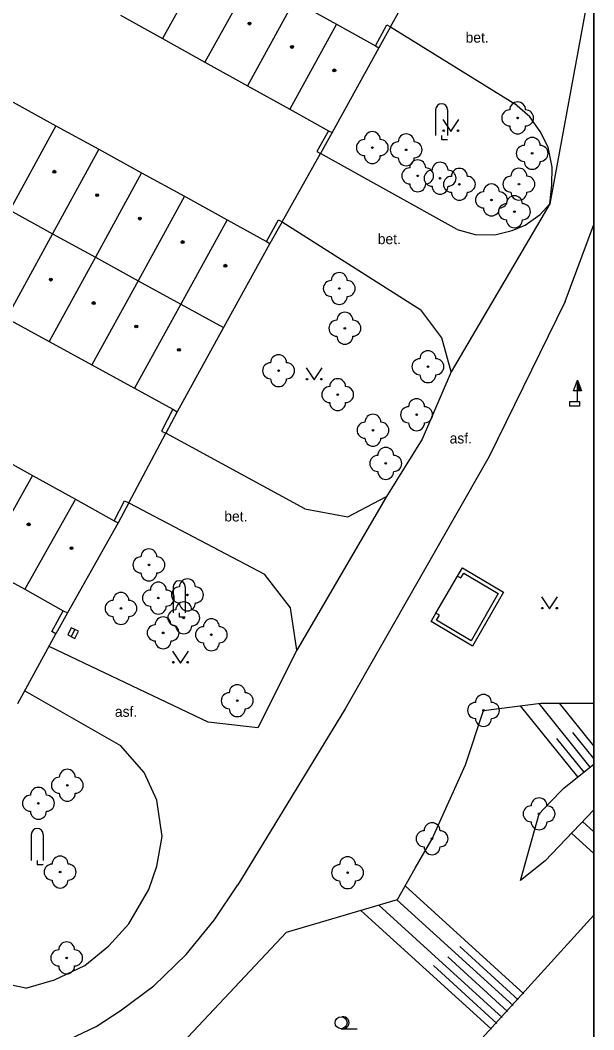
# Model space of a CAD drawing. Extents: x -598233 to -596890, y -1157848 to -1156431.
# Drawn here: x -596926.4 to -596890.5, y -1157763.6 to -1157700.3 of the extents above; entities that cross this region are included whole.
import ezdxf

# ---------------------------------------------------------------- set-up
doc = ezdxf.new("R2010")
doc.units = 0
for name, color, linetype in [('Level 10', 7, 'Continuous'), ('Level 11', 7, 'Continuous'), ('Level 14', 7, 'Continuous'), ('Level 15', 7, 'Continuous'), ('Level 22', 7, 'Continuous'), ('Level 24', 7, 'Continuous'), ('Level 25', 7, 'Continuous'), ('Level 27', 7, 'Continuous'), ('Level 36', 7, 'Continuous'), ('Level 39', 7, 'Continuous'), ('Level 40', 7, 'Continuous'), ('Level 5', 7, 'Continuous'), ('Level 7', 7, 'Continuous'), ('Level 8', 7, 'Continuous'), ('Vrstva 60', 7, 'Continuous'), ('zajmove_uzemi', 7, 'Continuous')]:
    doc.layers.add(name, color=color, linetype=linetype)

msp = doc.modelspace()

# ---------------------------------------------------------------- linework, layer by layer
at = {"layer": 'Level 10'}
msp.add_line((-596892.26, -1157717.92), (-596890.4624, -1157713.1005), dxfattribs=at)
for points in [[(-596903.2, -1157700.71), (-596895.4, -1157705.54)], [(-596893.21, -1157711.8), (-596893.1, -1157710.63), (-596893.07, -1157709.5), (-596893.32, -1157708.26), (-596893.82, -1157707.26), (-596894.4699, -1157706.35), (-596895.4, -1157705.54)], [(-596899.01, -1157713.4099), (-596907.58, -1157708.64)], [(-596899.01, -1157713.4099), (-596897.9, -1157713.7199), (-596896.6599, -1157713.74), (-596895.57, -1157713.48), (-596894.75, -1157713.13), (-596893.82, -1157712.4699), (-596893.21, -1157711.8)], [(-596909.98, -1157712.93), (-596901.29, -1157718.44)], [(-596892.26, -1157717.92), (-596897.01, -1157727.64), (-596906.03, -1157743.46), (-596912.75, -1157754.48)], [(-596899.39, -1157722.34), (-596899.9699, -1157720.21), (-596901.29, -1157718.44)], [(-596899.39, -1157722.34), (-596901.2199, -1157726.56), (-596903.45, -1157730.14)], [(-596908.55, -1157730.9099), (-596917.27, -1157726.17)], [(-596908.55, -1157730.9099), (-596905.87, -1157731.42), (-596903.45, -1157730.14)], [(-596919.58, -1157730.55), (-596911.09, -1157735.01)], [(-596909.06, -1157739.77), (-596909.45, -1157737.12), (-596911.09, -1157735.01)], [(-596909.06, -1157739.77), (-596911.49, -1157744.65), (-596914.61, -1157744.29), (-596924.57, -1157739.54)], [(-596926.09, -1157742.33), (-596920.11, -1157745.75)], [(-596926.02, -1157760.95), (-596924.23, -1157760.44), (-596922.34, -1157759.53), (-596920.82, -1157758.31), (-596919.57, -1157756.93), (-596918.33, -1157754.78), (-596917.83, -1157753.31), (-596917.5, -1157751.45), (-596917.82, -1157749.18), (-596918.62, -1157747.44), (-596920.11, -1157745.75)], [(-596926.87, -1157764.92), (-596923.3, -1157764.1599), (-596921.63, -1157763.36), (-596920.12, -1157762.37), (-596918.01, -1157760.8), (-596915.99, -1157758.84), (-596914.23, -1157756.7), (-596912.75, -1157754.48)], [(-596926.02, -1157760.95), (-596935.48, -1157759)]]:
    msp.add_lwpolyline(points, dxfattribs=at)
at = {"layer": 'Level 11'}
msp.add_line((-596890.4624, -1157696.83), (-596893.21, -1157711.8), dxfattribs=at)
for points in [[(-596893.21, -1157711.8), (-596899.39, -1157722.34)], [(-596903.45, -1157730.14), (-596909.06, -1157739.77)], [(-596900.35, -1157737.46), (-596898.99, -1157735.13)]]:
    msp.add_lwpolyline(points, dxfattribs=at)
at = {"layer": 'Level 14'}
for points in [[(-596900.59, -1157751.59), (-596898.5, -1157746.96), (-596897.37, -1157743.55), (-596893.77, -1157743.1), (-596890.4624, -1157743.0861)], [(-596893.27, -1157749.39), (-596892.32, -1157748.41), (-596890.4624, -1157746.9178)], [(-596895.06, -1157754.21), (-596893.89, -1157750.03), (-596893.27, -1157749.39)], [(-596890.4624, -1157749.7778), (-596893.51, -1157752.97), (-596895.06, -1157754.21)], [(-596901.64, -1157753.43), (-596900.59, -1157751.59)], [(-596931.46, -1157795.75), (-596930.64, -1157790), (-596929.99, -1157784.52), (-596931.05, -1157778.72), (-596927.22, -1157770.82), (-596926.09, -1157769.73), (-596923.59, -1157770.16), (-596920.73, -1157768.54), (-596916.2, -1157764.35), (-596909.71, -1157757.45), (-596902.75, -1157755.4), (-596901.64, -1157753.43)]]:
    msp.add_lwpolyline(points, dxfattribs=at)
at = {"layer": 'Level 15'}
for p, q in [((-596890.4624, -1157745.7706), (-596892.61, -1157743.1)), ((-596890.4624, -1157746.5656), (-596891.77, -1157744.94)), ((-596890.4624, -1157749.8159), (-596890.48, -1157749.8)), ((-596890.4624, -1157751.1628), (-596891.17, -1157750.52)), ((-596890.4624, -1157752.5105), (-596891.86, -1157751.24))]:
    msp.add_line(p, q, dxfattribs=at)
for points in [[(-596891.46, -1157747.72), (-596895.05, -1157743.26)], [(-596890.68, -1157747.1), (-596893.88, -1157743.11)], [(-596891.07, -1157747.41), (-596892.77, -1157745.3)], [(-596894.85, -1157761.32), (-596902.27, -1157754.55)], [(-596895.52, -1157762.05), (-596902.8, -1157755.42)], [(-596896.87, -1157763.53), (-596905.05, -1157756.08)], [(-596896.2, -1157762.79), (-596903.92, -1157755.75)], [(-596895.19, -1157761.68), (-596898.85, -1157758.34)], [(-596895.86, -1157762.42), (-596899.61, -1157759)], [(-596896.54, -1157763.16), (-596900.51, -1157759.54)]]:
    msp.add_lwpolyline(points, dxfattribs=at)
at = {"layer": 'Level 22'}
for centre in [(-596895.23, -1157706.42), (-596904.33, -1157708.28), (-596902.21, -1157708.42), (-596894.32, -1157708.64), (-596901.49, -1157710.05), (-596900.09, -1157710.2), (-596898.88, -1157710.58), (-596895.15, -1157710.57), (-596896.87, -1157711.56), (-596895.43, -1157712.3), (-596906.4, -1157717.11), (-596906.05, -1157719.6), (-596900.85, -1157722.01), (-596910.2, -1157722.26), (-596906.5, -1157723.76), (-596901.56, -1157725.02), (-596904.29, -1157725.99), (-596903.49, -1157728.07), (-596918.32, -1157734.43), (-596917.73, -1157736.51), (-596915.91, -1157736.31), (-596920.07, -1157737.16), (-596916.14, -1157737.75), (-596917.43, -1157738.69), (-596914.41, -1157738.81), (-596912.79, -1157742.94), (-596897.37, -1157743.55), (-596923.43, -1157748.24), (-596925.24, -1157749.37), (-596893.89, -1157750.03), (-596900.59, -1157751.59), (-596923.88, -1157753.68), (-596905.88, -1157753.72), (-596923.47, -1157759.06)]:
    msp.add_circle(centre, 0.05, dxfattribs=at)
for centre, start, end in [((-596895.23, -1157705.92), 0, 180), ((-596895.73, -1157706.42), 90, 270), ((-596894.73, -1157706.42), 270, 90), ((-596904.33, -1157707.78), 0, 180), ((-596902.21, -1157707.92), 0, 180), ((-596895.23, -1157706.92), 180, 0), ((-596904.83, -1157708.28), 90, 270), ((-596903.83, -1157708.28), 270, 90), ((-596902.71, -1157708.42), 90, 270), ((-596901.71, -1157708.42), 270, 90), ((-596894.32, -1157708.14), 0, 180), ((-596894.82, -1157708.64), 90, 270), ((-596893.82, -1157708.64), 270, 90), ((-596904.33, -1157708.78), 180, 0), ((-596902.21, -1157708.92), 180, 0), ((-596901.49, -1157709.55), 0, 180), ((-596900.09, -1157709.7), 0, 180), ((-596894.32, -1157709.14), 180, 0), ((-596901.99, -1157710.05), 90, 270), ((-596900.59, -1157710.2), 90, 270), ((-596900.99, -1157710.05), 270, 90), ((-596899.59, -1157710.2), 270, 90), ((-596898.88, -1157710.08), 0, 180), ((-596895.15, -1157710.07), 0, 180), ((-596901.49, -1157710.55), 180, 0), ((-596899.38, -1157710.58), 90, 270), ((-596898.38, -1157710.58), 270, 90), ((-596896.87, -1157711.06), 0, 180), ((-596895.65, -1157710.57), 90, 270), ((-596894.65, -1157710.57), 270, 90), ((-596900.09, -1157710.7), 180, 0), ((-596898.88, -1157711.08), 180, 0), ((-596897.37, -1157711.56), 90, 270), ((-596896.37, -1157711.56), 270, 90), ((-596895.15, -1157711.07), 180, 0), ((-596895.93, -1157712.3), 90, 270), ((-596895.43, -1157711.8), 0, 180), ((-596894.93, -1157712.3), 270, 90), ((-596896.87, -1157712.06), 180, 0), ((-596895.43, -1157712.8), 180, 0), ((-596906.4, -1157716.61), 0, 180), ((-596906.9, -1157717.11), 90, 270), ((-596905.9, -1157717.11), 270, 90), ((-596906.4, -1157717.61), 180, 0), ((-596906.05, -1157719.1), 0, 180), ((-596906.55, -1157719.6), 90, 270), ((-596905.55, -1157719.6), 270, 90), ((-596906.05, -1157720.1), 180, 0), ((-596910.2, -1157721.76), 0, 180), ((-596900.85, -1157721.51), 0, 180), ((-596910.7, -1157722.26), 90, 270), ((-596909.7, -1157722.26), 270, 90), ((-596901.35, -1157722.01), 90, 270), ((-596900.35, -1157722.01), 270, 90), ((-596900.85, -1157722.51), 180, 0), ((-596910.2, -1157722.76), 180, 0), ((-596907, -1157723.76), 90, 270), ((-596906.5, -1157723.26), 0, 180), ((-596906, -1157723.76), 270, 90), ((-596906.5, -1157724.26), 180, 0), ((-596902.06, -1157725.02), 90, 270), ((-596901.56, -1157724.52), 0, 180), ((-596901.06, -1157725.02), 270, 90), ((-596904.29, -1157725.49), 0, 180), ((-596904.79, -1157725.99), 90, 270), ((-596903.79, -1157725.99), 270, 90), ((-596901.56, -1157725.52), 180, 0), ((-596904.29, -1157726.49), 180, 0), ((-596903.49, -1157727.57), 0, 180), ((-596903.99, -1157728.07), 90, 270), ((-596902.99, -1157728.07), 270, 90), ((-596903.49, -1157728.57), 180, 0), ((-596918.32, -1157733.93), 0, 180), ((-596918.82, -1157734.43), 90, 270), ((-596917.82, -1157734.43), 270, 90), ((-596918.32, -1157734.93), 180, 0), ((-596915.91, -1157735.81), 0, 180), ((-596917.73, -1157736.01), 0, 180), ((-596916.41, -1157736.31), 90, 270), ((-596915.41, -1157736.31), 270, 90), ((-596920.07, -1157736.66), 0, 180), ((-596918.23, -1157736.51), 90, 270), ((-596917.23, -1157736.51), 270, 90), ((-596920.57, -1157737.16), 90, 270), ((-596919.57, -1157737.16), 270, 90), ((-596917.73, -1157737.01), 180, 0), ((-596916.14, -1157737.25), 0, 180), ((-596915.91, -1157736.81), 180, 0), ((-596920.07, -1157737.66), 180, 0), ((-596917.43, -1157738.19), 0, 180), ((-596916.64, -1157737.75), 90, 270), ((-596915.64, -1157737.75), 270, 90), ((-596914.41, -1157738.31), 0, 180), ((-596917.93, -1157738.69), 90, 270), ((-596916.93, -1157738.69), 270, 90), ((-596916.14, -1157738.25), 180, 0), ((-596914.91, -1157738.81), 90, 270), ((-596913.91, -1157738.81), 270, 90), ((-596917.43, -1157739.19), 180, 0), ((-596914.41, -1157739.31), 180, 0), ((-596912.79, -1157742.44), 0, 180), ((-596913.29, -1157742.94), 90, 270), ((-596912.29, -1157742.94), 270, 90), ((-596897.37, -1157743.05), 0, 180), ((-596912.79, -1157743.44), 180, 0), ((-596897.87, -1157743.55), 90, 270), ((-596896.87, -1157743.55), 270, 90), ((-596897.37, -1157744.05), 180, 0), ((-596923.43, -1157747.74), 0, 180), ((-596923.93, -1157748.24), 90, 270), ((-596922.93, -1157748.24), 270, 90), ((-596925.24, -1157748.87), 0, 180), ((-596925.74, -1157749.37), 90, 270), ((-596924.74, -1157749.37), 270, 90), ((-596923.43, -1157748.74), 180, 0), ((-596893.89, -1157749.53), 0, 180), ((-596925.24, -1157749.87), 180, 0), ((-596894.39, -1157750.03), 90, 270), ((-596893.39, -1157750.03), 270, 90), ((-596901.09, -1157751.59), 90, 270), ((-596900.59, -1157751.09), 0, 180), ((-596900.09, -1157751.59), 270, 90), ((-596893.89, -1157750.53), 180, 0), ((-596900.59, -1157752.09), 180, 0), ((-596923.88, -1157753.18), 0, 180), ((-596905.88, -1157753.22), 0, 180), ((-596924.38, -1157753.68), 90, 270), ((-596923.38, -1157753.68), 270, 90), ((-596906.38, -1157753.72), 90, 270), ((-596905.38, -1157753.72), 270, 90), ((-596923.88, -1157754.18), 180, 0), ((-596905.88, -1157754.22), 180, 0), ((-596923.47, -1157758.56), 0, 180), ((-596923.97, -1157759.06), 90, 270), ((-596922.97, -1157759.06), 270, 90), ((-596923.47, -1157759.56), 180, 0)]:
    msp.add_arc(centre, 0.5, start, end, dxfattribs=at)
at = {"layer": 'Level 24'}
msp.add_lwpolyline([(-596891.36, -1157724.19), (-596891.36, -1157724.49), (-596891.96, -1157724.49), (-596891.96, -1157724.19), (-596891.36, -1157724.19)], dxfattribs=at)
at = {"layer": 'Level 25'}
for p, q in [((-596891.742, -1157723.528), (-596891.49, -1157722.854)), ((-596891.49, -1157723.528), (-596891.742, -1157723.528)), ((-596891.49, -1157724.18), (-596891.49, -1157723.53))]:
    msp.add_line(p, q, dxfattribs=at)
for points in [[(-596891.24, -1157723.53), (-596891.49, -1157723.53), (-596891.49, -1157722.854), (-596891.49, -1157722.854)], [(-596891.297, -1157723.49), (-596891.45, -1157723.49), (-596891.45, -1157723.077)], [(-596891.355, -1157723.45), (-596891.41, -1157723.45), (-596891.41, -1157723.301)]]:
    msp.add_lwpolyline(points, close=True, dxfattribs=at)
at = {"layer": 'Level 27'}
msp.add_line((-596923.1775, -1157738.9257), (-596922.9625, -1157738.4743), dxfattribs=at)
msp.add_lwpolyline([(-596922.9517, -1157739.0332), (-596922.7368, -1157738.5817), (-596923.1883, -1157738.3668), (-596923.4032, -1157738.8183)], close=True, dxfattribs=at)
at = {"layer": 'Level 36'}
for p, q in [((-596900.365, -1157705.905), (-596900.365, -1157707.53)), ((-596899.615, -1157705.905), (-596899.615, -1157707.53)), ((-596916.795, -1157735.805), (-596916.795, -1157737.43)), ((-596916.045, -1157735.805), (-596916.045, -1157737.43)), ((-596925.685, -1157751.325), (-596925.685, -1157752.95)), ((-596924.935, -1157751.325), (-596924.935, -1157752.95)), ((-596906.29, -1157763.495), (-596905.29, -1157763.495))]:
    msp.add_line(p, q, dxfattribs=at)
for points in [[(-596899.91, -1157706.52), (-596899.41, -1157707.27), (-596898.91, -1157706.52)], [(-596899.99, -1157707.53), (-596899.99, -1157707.78), (-596899.615, -1157707.78)], [(-596908.4699, -1157722.09), (-596907.9699, -1157722.84), (-596907.4699, -1157722.09)], [(-596893.73, -1157736.44), (-596893.23, -1157737.19), (-596892.73, -1157736.44)], [(-596916.42, -1157737.43), (-596916.42, -1157737.68), (-596916.045, -1157737.68)], [(-596916.84, -1157739.83), (-596916.34, -1157740.58), (-596915.84, -1157739.83)], [(-596925.31, -1157752.95), (-596925.31, -1157753.2), (-596924.935, -1157753.2)]]:
    msp.add_lwpolyline(points, dxfattribs=at)
for centre, radius in [((-596899.8602, -1157707.2198), 0.05), ((-596898.9608, -1157707.2198), 0.05), ((-596908.4201, -1157722.7898), 0.05), ((-596907.5207, -1157722.7898), 0.05), ((-596893.6802, -1157737.1398), 0.05), ((-596892.7808, -1157737.1398), 0.05), ((-596916.7902, -1157740.5298), 0.05), ((-596915.8908, -1157740.5298), 0.05), ((-596906.29, -1157763.1196), 0.375)]:
    msp.add_circle(centre, radius, dxfattribs=at)
for centre, start, end in [((-596899.9903, -1157705.9046), 0, 180), ((-596916.4203, -1157735.8046), 0, 180), ((-596925.3103, -1157751.3246), 0, 180), ((-596906.165, -1157763.1196), 260.405931, 99.594069)]:
    msp.add_arc(centre, 0.375, start, end, dxfattribs=at)
at = {"layer": 'Level 39'}
for centre, radius in [((-596912.02, -1157700.51), 0.09), ((-596912.02, -1157700.51), 0.0398), ((-596909.36, -1157701.9699), 0.09), ((-596909.36, -1157701.9699), 0.0398), ((-596906.71, -1157703.44), 0.09), ((-596906.71, -1157703.44), 0.0398), ((-596924.24, -1157709.79), 0.09), ((-596924.24, -1157709.79), 0.0398), ((-596921.56, -1157711.26), 0.09), ((-596921.56, -1157711.26), 0.0398), ((-596918.89, -1157712.73), 0.09), ((-596918.89, -1157712.73), 0.0398), ((-596916.21, -1157714.2), 0.09), ((-596916.21, -1157714.2), 0.0398), ((-596913.53, -1157715.68), 0.09), ((-596913.53, -1157715.68), 0.0398), ((-596924.46, -1157716.55), 0.09), ((-596924.46, -1157716.55), 0.0398), ((-596921.78, -1157718.02), 0.09), ((-596921.78, -1157718.02), 0.0398), ((-596919.11, -1157719.49), 0.09), ((-596919.11, -1157719.49), 0.0398), ((-596916.44, -1157720.95), 0.09), ((-596916.44, -1157720.95), 0.0398), ((-596925.85, -1157731.89), 0.09), ((-596925.85, -1157731.89), 0.0398), ((-596923.17, -1157733.38), 0.09), ((-596923.17, -1157733.38), 0.0398)]:
    msp.add_circle(centre, radius, dxfattribs=at)
at = {"layer": 'Level 5'}
for points in [[(-596914.53, -1157696.14), (-596917.46, -1157701.45)], [(-596911.88, -1157697.61), (-596914.81, -1157702.92)], [(-596909.2199, -1157699.08), (-596912.15, -1157704.4)], [(-596909.2199, -1157699.08), (-596906.57, -1157700.55)], [(-596920.11, -1157699.98), (-596917.46, -1157701.45)], [(-596906.57, -1157700.55), (-596909.5, -1157705.87)], [(-596906.57, -1157700.55), (-596904.14, -1157701.9)], [(-596917.46, -1157701.45), (-596914.81, -1157702.92)], [(-596903.92, -1157702.02), (-596906.85, -1157707.34)], [(-596904.14, -1157701.9), (-596903.92, -1157702.02)], [(-596914.81, -1157702.92), (-596912.15, -1157704.4)], [(-596912.15, -1157704.4), (-596909.5, -1157705.87)], [(-596926.82, -1157705.44), (-596924.14, -1157706.9099)], [(-596909.5, -1157705.87), (-596907.07, -1157707.2199)], [(-596924.14, -1157706.9099), (-596927.02, -1157712.2)], [(-596924.14, -1157706.9099), (-596921.46, -1157708.38)], [(-596907.07, -1157707.2199), (-596906.85, -1157707.34)], [(-596921.46, -1157708.38), (-596924.35, -1157713.68)], [(-596921.46, -1157708.38), (-596918.78, -1157709.86)], [(-596918.78, -1157709.86), (-596921.67, -1157715.15)], [(-596918.78, -1157709.86), (-596916.1, -1157711.33)], [(-596916.1, -1157711.33), (-596919, -1157716.62)], [(-596916.1, -1157711.33), (-596913.42, -1157712.81)], [(-596927.02, -1157712.2), (-596924.35, -1157713.68)], [(-596913.42, -1157712.81), (-596916.33, -1157718.09)], [(-596913.42, -1157712.81), (-596910.96, -1157714.1599)], [(-596924.35, -1157713.68), (-596927.24, -1157718.96)], [(-596924.35, -1157713.68), (-596921.67, -1157715.15)], [(-596910.74, -1157714.28), (-596913.65, -1157719.56)], [(-596910.96, -1157714.1599), (-596910.74, -1157714.28)], [(-596921.67, -1157715.15), (-596924.57, -1157720.43)], [(-596921.67, -1157715.15), (-596919, -1157716.62)], [(-596919, -1157716.62), (-596921.9, -1157721.9)], [(-596919, -1157716.62), (-596916.33, -1157718.09)], [(-596916.33, -1157718.09), (-596919.23, -1157723.36)], [(-596916.33, -1157718.09), (-596913.65, -1157719.56)], [(-596927.24, -1157718.96), (-596924.57, -1157720.43)], [(-596913.65, -1157719.56), (-596916.56, -1157724.83)], [(-596924.57, -1157720.43), (-596921.9, -1157721.9)], [(-596921.9, -1157721.9), (-596919.23, -1157723.36)], [(-596919.23, -1157723.36), (-596916.82, -1157724.68)], [(-596916.82, -1157724.68), (-596916.56, -1157724.83)], [(-596928.28, -1157727.35), (-596925.6, -1157728.83)], [(-596925.6, -1157728.83), (-596928.78, -1157734.49)], [(-596925.6, -1157728.83), (-596922.92, -1157730.32)], [(-596922.92, -1157730.32), (-596926.1, -1157735.96)], [(-596922.92, -1157730.32), (-596920.5, -1157731.6599)], [(-596920.24, -1157731.8), (-596923.42, -1157737.44)], [(-596920.5, -1157731.6599), (-596920.24, -1157731.8)], [(-596928.78, -1157734.49), (-596926.1, -1157735.96)], [(-596926.1, -1157735.96), (-596923.68, -1157737.3)], [(-596923.68, -1157737.3), (-596923.42, -1157737.44)]]:
    msp.add_lwpolyline(points, dxfattribs=at)
at = {"layer": 'Level 7'}
for points in [[(-596904.14, -1157701.9), (-596903.42, -1157700.58), (-596903.2, -1157700.71)], [(-596903.2, -1157700.71), (-596903.92, -1157702.02)], [(-596907.07, -1157707.2199), (-596907.8, -1157708.52), (-596907.58, -1157708.64)], [(-596906.85, -1157707.34), (-596907.58, -1157708.64)], [(-596910.96, -1157714.1599), (-596910.2, -1157712.81), (-596909.98, -1157712.93)], [(-596909.98, -1157712.93), (-596910.74, -1157714.28)], [(-596916.82, -1157724.68), (-596917.54, -1157726.04), (-596917.27, -1157726.17)], [(-596916.56, -1157724.83), (-596917.27, -1157726.17)], [(-596920.5, -1157731.6599), (-596919.84, -1157730.4099), (-596919.58, -1157730.55)], [(-596919.58, -1157730.55), (-596920.24, -1157731.8)], [(-596898.69, -1157734.61), (-596896.11, -1157736.14), (-596898.06, -1157739.52), (-596900.65, -1157737.98), (-596900.35, -1157737.46)], [(-596898.99, -1157735.13), (-596898.69, -1157734.61)], [(-596898.99, -1157735.13), (-596898.78, -1157735.25), (-596898.6, -1157734.95), (-596896.45, -1157736.23), (-596898.15, -1157739.18), (-596900.31, -1157737.89), (-596900.13, -1157737.59), (-596900.35, -1157737.46)], [(-596924.14, -1157738.75), (-596924.4, -1157738.61), (-596923.68, -1157737.3)], [(-596923.42, -1157737.44), (-596924.14, -1157738.75)], [(-596897.9, -1157817.51), (-596909.48, -1157809.4699), (-596912.57, -1157782.67), (-596909.01, -1157776.84), (-596890.4624, -1157756.3809)]]:
    msp.add_lwpolyline(points, dxfattribs=at)
at = {"layer": 'Level 8'}
for points in [[(-596903.2, -1157700.71), (-596900.78, -1157696.34)], [(-596909.98, -1157712.93), (-596907.58, -1157708.64)], [(-596919.58, -1157730.55), (-596917.27, -1157726.17)], [(-596926.52, -1157743.12), (-596924.14, -1157738.75)]]:
    msp.add_lwpolyline(points, dxfattribs=at)
at = {"layer": 'Vrstva 60'}
msp.add_lwpolyline([(-597043.89, -1157728.64), (-596966.78, -1157770.59), (-596991, -1157796.97), (-596991.35, -1157797.35), (-596994.58, -1157800.82), (-596995.24, -1157801.52), (-596996.93, -1157803.34), (-596977.24, -1157811.71), (-596955.68, -1157822.54), (-596954.88, -1157822.94), (-596954.53, -1157823.11), (-596950.75, -1157824.98), (-596940.73, -1157829.95), (-596923.64, -1157838.41), (-596922.24, -1157838.15), (-596916.44, -1157837.09), (-596909.03, -1157835.74), (-596905.06, -1157838.46), (-596899.87, -1157842.03), (-596893.48, -1157846.41), (-596890.4817, -1157848.4611), (-596890.4624, -1157848.4611), (-596890.4624, -1156430.8558)], dxfattribs=at)
at = {"layer": 'zajmove_uzemi'}
msp.add_lwpolyline([(-598232.8901, -1156430.8558), (-596890.4624, -1156430.8558), (-596890.4624, -1157848.4611), (-598232.8901, -1157848.4611)], close=True, dxfattribs=at)

# ---------------------------------------------------------------- texts
at = {"layer": 'Level 40'}
for s, p in [('bet.', (-596898.49, -1157701.7)), ('bet.', (-596903.99, -1157714.33)), ('asf.', (-596899.49, -1157726.82)), ('bet.', (-596913.6, -1157731.71)), ('asf.', (-596920.45, -1157743.95))]:
    msp.add_text(s, height=0.65, dxfattribs=at).set_placement(p)

doc.saveas('drawing.dxf')
